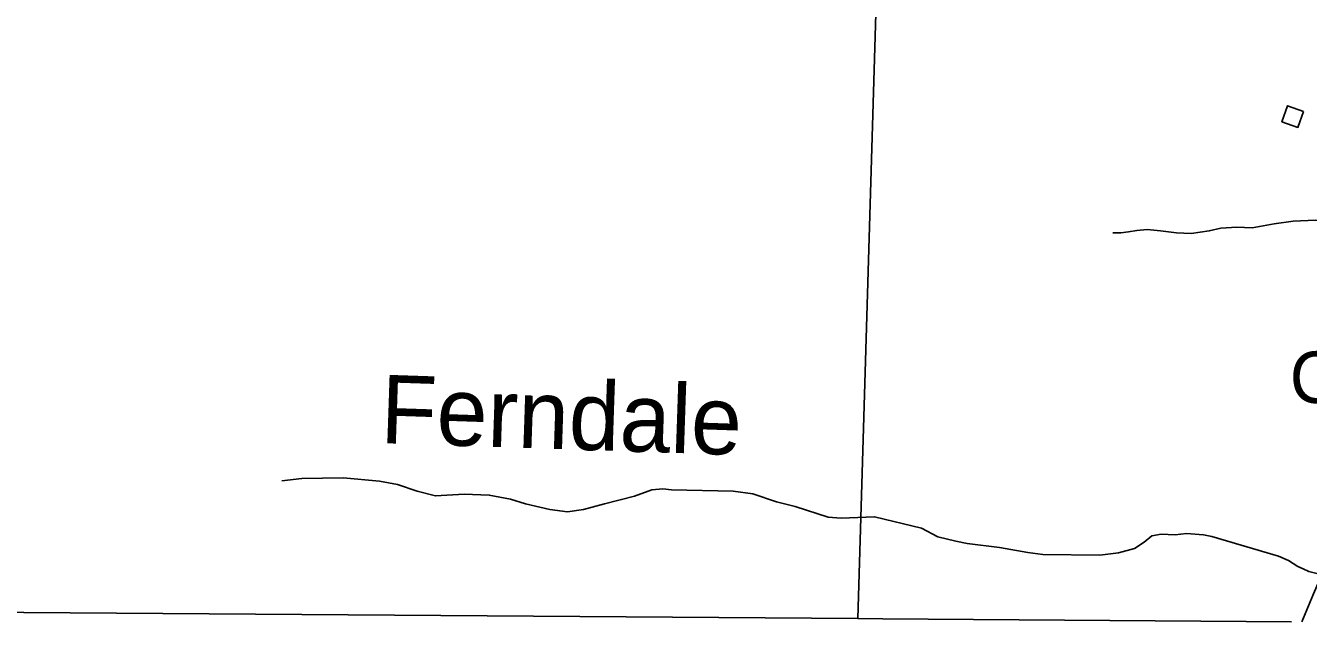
# Model space of a CAD drawing. Extents: x -19 to 366, y -4 to 359.
# Drawn here: x 136.395 to 137.894, y 192.02 to 192.721 of the extents above; entities that cross this region are included whole.
import ezdxf

# ---------------------------------------------------------------- set-up
doc = ezdxf.new("R2010")
doc.units = 0
for name, color, linetype in [('Level 2', 7, 'Continuous'), ('Level 31', 7, 'Continuous'), ('Level 35', 7, 'Continuous'), ('Level 5', 7, 'Continuous'), ('Level 56', 7, 'Continuous'), ('Level 57', 7, 'Continuous'), ('Level 60', 7, 'Continuous')]:
    doc.layers.add(name, color=color, linetype=linetype)

msp = doc.modelspace()

# ---------------------------------------------------------------- linework, layer by layer
at = {"layer": 'Level 2'}
msp.add_lwpolyline([(133.9509, 192.0638), (134.386, 192.0586), (134.4263, 192.0586), (135.372, 192.0471), (135.4008, 192.0467), (136.3634, 192.0352), (136.3927, 192.035), (137.3674, 192.0278), (137.3965, 192.0275), (137.874, 192.0242)], dxfattribs=at)
at = {"layer": 'Level 31'}
msp.add_lwpolyline([(137.9285, 192.1116), (137.9275, 192.1106), (137.9231, 192.1052), (137.9198, 192.0998), (137.9155, 192.0924), (137.9118, 192.0843), (137.8997, 192.057), (137.8861, 192.0241)], dxfattribs=at)
at = {"layer": 'Level 35'}
for points in [[(138.0539, 192.4886), (138.053, 192.4884), (138.0436, 192.4889), (138.0288, 192.4911), (137.9927, 192.4918), (137.9721, 192.4908), (137.9532, 192.4898), (137.9307, 192.4923), (137.9021, 192.4936), (137.8761, 192.4924), (137.8539, 192.4893), (137.8279, 192.4845), (137.8101, 192.4853), (137.7916, 192.4843), (137.7779, 192.481), (137.7568, 192.4779), (137.7396, 192.4788), (137.7209, 192.4809), (137.7053, 192.4824), (137.6933, 192.4812), (137.6837, 192.48), (137.6746, 192.4785), (137.6652, 192.4787)], [(137.8878, 192.086), (137.8813, 192.0889), (137.8706, 192.0956), (137.8588, 192.1007), (137.8151, 192.1136), (137.781, 192.124), (137.7711, 192.1258), (137.7514, 192.1273), (137.7382, 192.1256), (137.7216, 192.1264), (137.7107, 192.1247), (137.7017, 192.117), (137.6905, 192.1096), (137.6717, 192.1047), (137.6502, 192.1021), (137.5833, 192.1028), (137.5659, 192.1052), (137.5326, 192.1111), (137.4951, 192.1157), (137.4818, 192.1182), (137.4609, 192.1235), (137.4415, 192.1334), (137.3868, 192.1469), (137.3476, 192.1451), (137.3324, 192.1464), (137.294, 192.159), (137.272, 192.1643), (137.2447, 192.1737), (137.2216, 192.1767), (137.1494, 192.1785), (137.1395, 192.1795), (137.1263, 192.1782), (137.1064, 192.171), (137.0711, 192.162), (137.0466, 192.1552), (137.0281, 192.1526), (137.0073, 192.1553), (136.9789, 192.162), (136.9614, 192.1674), (136.9364, 192.1723), (136.9072, 192.1733), (136.8736, 192.1712), (136.8524, 192.1769), (136.8292, 192.1845), (136.8084, 192.1883), (136.7656, 192.1925), (136.7176, 192.1917), (136.6939, 192.189)], [(137.9069, 192.0797), (137.8944, 192.0831), (137.8878, 192.086)]]:
    msp.add_lwpolyline(points, dxfattribs=at)
at = {"layer": 'Level 5'}
msp.add_lwpolyline([(137.3674, 192.0278), (137.3969, 193.0228)], dxfattribs=at)
at = {"layer": 'Level 56'}
msp.add_lwpolyline([(137.888, 192.6206), (137.8815, 192.6019), (137.8629, 192.6085), (137.8694, 192.6271)], close=True, dxfattribs=at)
at = {"layer": 'Level 60'}
for points in [[(139.4406, 1.5315), (139.2511, 10.1473), (139.0608, 18.7633), (138.8699, 27.3793), (138.6784, 35.9956), (138.4861, 44.6119), (138.2932, 53.2285), (138.0997, 61.8451), (137.9055, 70.4619), (137.7106, 79.0789), (137.5151, 87.6959), (137.319, 96.3132), (137.1221, 104.9306), (136.9247, 113.5481), (136.7265, 122.1658), (136.5278, 130.7836), (136.3283, 139.4016), (136.1282, 148.0197), (135.9275, 156.6379), (135.7261, 165.2564), (135.5241, 173.8749), (135.3214, 182.4936), (135.1181, 191.1125), (134.9141, 199.7315), (134.7095, 208.3506), (134.5043, 216.9699), (134.2984, 225.5894), (134.0919, 234.209), (133.8847, 242.8288), (133.6769, 251.4487), (133.4685, 260.0687), (133.2594, 268.6889), (133.0497, 277.3093), (132.8393, 285.9298), (132.6283, 294.5504), (132.4167, 303.1713), (132.2044, 311.7922), (131.9916, 320.4133), (131.778, 329.0346), (131.5639, 337.656), (131.3491, 346.2776)], [(0, 189.5162), (7.1121, 189.5206), (14.2243, 189.5339), (21.3364, 189.556), (28.4484, 189.5869), (35.5605, 189.6267), (42.6725, 189.6754), (49.7844, 189.7329), (56.8962, 189.7992), (64.0079, 189.8744), (71.1196, 189.9584), (78.2311, 190.0512), (85.3425, 190.1529), (92.4538, 190.2635), (99.5649, 190.3829), (106.6759, 190.5111), (113.7867, 190.6482), (120.8974, 190.7941), (128.0078, 190.9489), (135.1181, 191.1125), (142.2282, 191.2849), (149.338, 191.4662), (156.4476, 191.6563), (163.5569, 191.8553), (170.666, 192.0631), (177.7749, 192.2798), (184.8835, 192.5053), (191.9917, 192.7396), (199.0997, 192.9828), (206.2074, 193.2348), (213.3147, 193.4956), (220.4218, 193.7653), (227.5285, 194.0438), (234.6348, 194.3312), (241.7408, 194.6274), (248.8464, 194.9324), (255.9516, 195.2463), (263.0564, 195.569), (270.1608, 195.9005), (277.2648, 196.2409), (284.3683, 196.5901), (291.4715, 196.9481), (298.5741, 197.315), (305.6763, 197.6907), (312.7781, 198.0753), (319.8793, 198.4686), (326.9801, 198.8708), (334.0804, 199.2818), (341.1801, 199.7017)]]:
    msp.add_spline(points, degree=3, dxfattribs=at)

# ---------------------------------------------------------------- texts
at = {"layer": 'Level 35'}
msp.add_text('Ferndale', height=0.08, rotation=358.091, dxfattribs=at).set_placement((136.8086, 192.233))
at = {"layer": 'Level 57'}
msp.add_text('CENTER', height=0.06, dxfattribs=at).set_placement((137.872, 192.2799))

doc.saveas('drawing.dxf')
